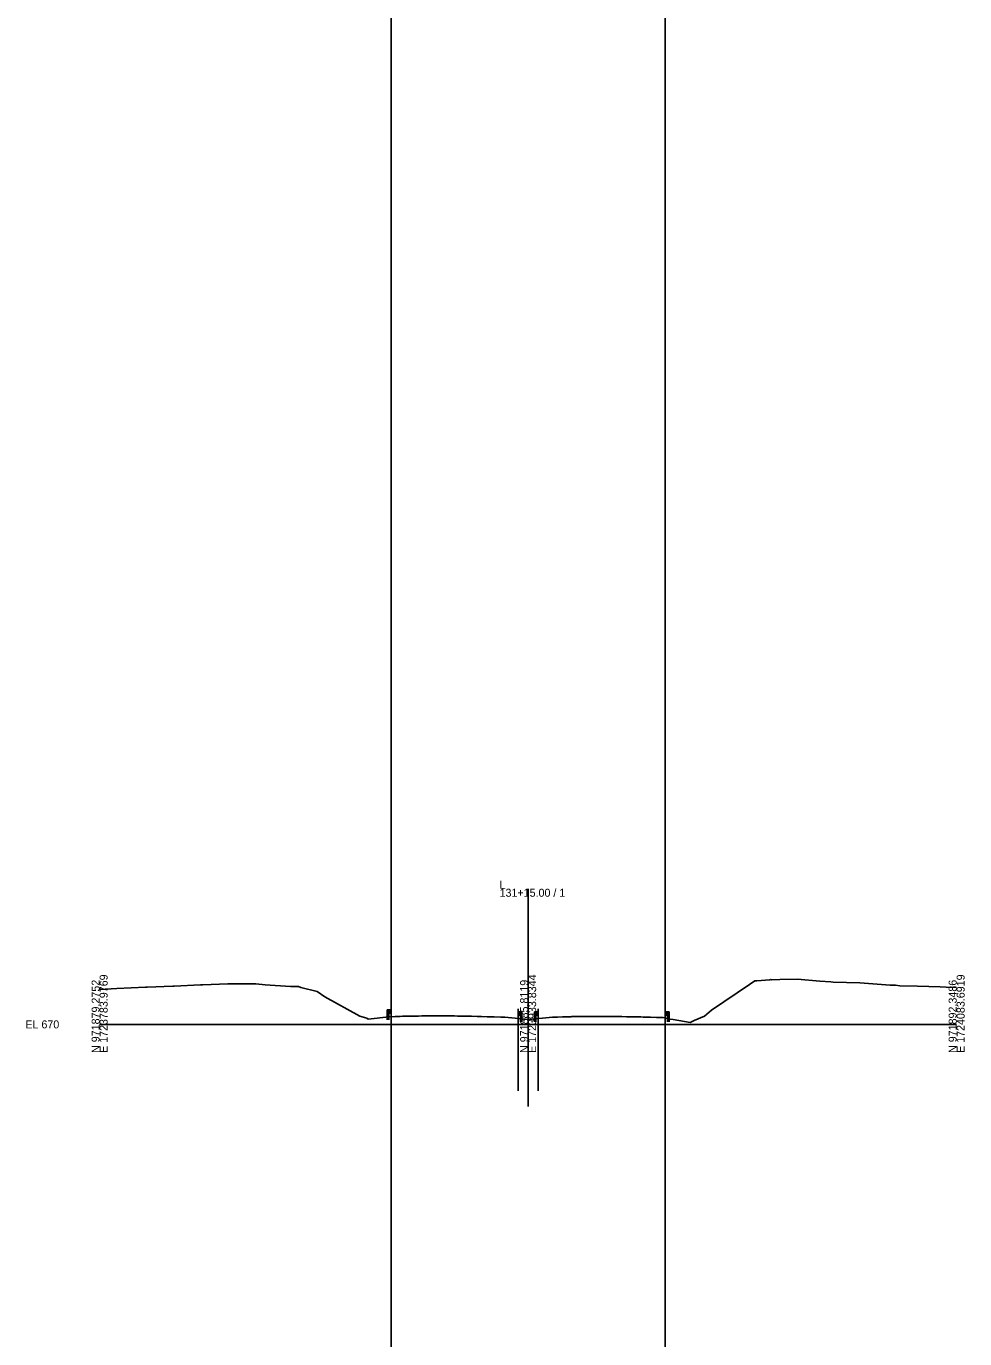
# Model space of a CAD drawing. Extents: x -26 to 303, y -29 to 15026.
# Drawn here: x -25.7 to 302.8, y 890 to 1349.3 of the extents above; entities that cross this region are included whole.
import ezdxf

# ---------------------------------------------------------------- set-up
doc = ezdxf.new("R2010")
doc.units = 0
for name, color, linetype in [('Exist Cross Section Cell', 7, 'Continuous'), ('Exist XS Center Line Elevation Label', 7, 'Continuous'), ('Exist XS Ground Line', 7, 'Continuous'), ('Scratch_Level_0', 7, 'Continuous'), ('Typical Guardrail CELL', 7, 'Continuous')]:
    doc.layers.add(name, color=color, linetype=linetype)

msp = doc.modelspace()

# ---------------------------------------------------------------- linework, layer by layer
at = {"layer": 'Exist Cross Section Cell'}
for p, q in [((150, 1000), (150, 1047.47)), ((0, 1000), (150, 1000)), ((150, 1000), (300, 1000))]:
    msp.add_line(p, q, dxfattribs=at)
at = {"layer": 'Exist XS Ground Line'}
msp.add_lwpolyline([(0, 1012.24), (6.04, 1012.58), (16.07, 1013.05), (16.68, 1013.07), (25.67, 1013.4), (26.06, 1013.41), (35.26, 1013.85), (36.07, 1013.89), (44.85, 1014.16), (46.52, 1014.19), (53.59, 1014.2), (54.66, 1014.22), (57.96, 1013.81), (66.81, 1013.3), (69.56, 1013.22), (70.38, 1012.9), (76.1, 1011.47), (78.82, 1009.59), (91.07, 1002.88), (93.5, 1002.17), (94.04, 1001.85), (101.24, 1002.61), (102.28, 1002.74), (102.9, 1002.7), (103.49, 1002.72), (105.22, 1002.81), (106, 1002.83), (107.72, 1002.88), (109.33, 1002.9), (110.23, 1002.91), (111.13, 1002.93), (111.66, 1002.93), (112.74, 1002.94), (113.82, 1002.95), (115.24, 1002.95), (116.44, 1002.96), (117.73, 1002.97), (119.05, 1002.98), (120.23, 1002.98), (121.31, 1002.98), (123.1, 1002.98), (124.18, 1002.96), (125.22, 1002.93), (126.88, 1002.9), (127.72, 1002.88), (129.51, 1002.84), (130.23, 1002.83), (132.16, 1002.78), (132.74, 1002.77), (133.28, 1002.75), (133.73, 1002.74), (135.69, 1002.68), (137.28, 1002.65), (137.77, 1002.63), (138.12, 1002.62), (140.49, 1002.57), (141.42, 1002.55), (141.84, 1002.51), (150.2, 1001.66), (158.53, 1002.54), (160.29, 1002.57), (162.08, 1002.62), (162.77, 1002.64), (163.57, 1002.67), (164.56, 1002.7), (164.89, 1002.7), (165.26, 1002.71), (166.89, 1002.72), (167.81, 1002.73), (168.79, 1002.74), (170.27, 1002.76), (171.67, 1002.77), (172.79, 1002.78), (174.01, 1002.79), (175.29, 1002.8), (176.76, 1002.8), (177.32, 1002.79), (178.29, 1002.78), (179.23, 1002.77), (180.28, 1002.75), (181.24, 1002.74), (182.78, 1002.71), (184.45, 1002.68), (185.27, 1002.67), (186.03, 1002.66), (187.79, 1002.63), (189.49, 1002.6), (190.28, 1002.57), (190.81, 1002.56), (192.81, 1002.51), (194.94, 1002.46), (195.45, 1002.45), (197.32, 1002.37), (198.25, 1002.16), (199.67, 1001.88), (200.74, 1001.72), (206.73, 1000.71), (208.16, 1001.37), (211.77, 1002.85), (214.23, 1004.96), (227.53, 1013.95), (229.3, 1015.26), (230.11, 1015.29), (234.56, 1015.59), (234.92, 1015.71), (235.26, 1015.65), (238.12, 1015.7), (244.33, 1015.82), (252.14, 1015.16), (256, 1014.88), (256.72, 1014.79), (266.15, 1014.56), (276.77, 1013.76), (278.63, 1013.68), (280.13, 1013.55), (286.29, 1013.35), (294.21, 1013.11), (296.3, 1012.99), (300, 1012.9)], dxfattribs=at)
at = {"layer": 'Scratch_Level_0'}
for p, q in [((102, 15009.56), (102, -28.7)), ((198, 15009.56), (198, -28.7)), ((146.46, 1005.5), (146.46, 976.8)), ((153.54, 1005.5), (153.54, 976.8)), ((150, 1000), (150, 971.3))]:
    msp.add_line(p, q, dxfattribs=at)
at = {"layer": 'Typical Guardrail CELL'}
for p, q in [((101.18, 1005.04), (100.68, 1005.04)), ((100.68, 1005.04), (100.68, 1002.55)), ((101.18, 1002.55), (100.68, 1002.55)), ((100.68, 1002.55), (100.68, 1001.54)), ((101.18, 1005.04), (101.18, 1002.55)), ((101.18, 1005.04), (101.68, 1005.04)), ((101.18, 1003.88), (101.68, 1003.88)), ((101.18, 1002.55), (101.18, 1001.54)), ((101.68, 1005.04), (101.68, 1003.88)), ((101.68, 1005.04), (101.97, 1004.83)), ((101.68, 1004.5), (101.97, 1004.71)), ((101.68, 1004.46), (101.68, 1004.5)), ((101.68, 1004.46), (101.68, 1004.41)), ((101.68, 1004.41), (101.97, 1004.21)), ((101.68, 1003.88), (101.97, 1004.08)), ((146.78, 1004.39), (146.49, 1004.19)), ((146.78, 1003.86), (146.49, 1004.06)), ((146.78, 1003.76), (146.49, 1003.56)), ((146.78, 1003.23), (146.49, 1003.43)), ((147.28, 1004.39), (146.78, 1004.39)), ((146.78, 1004.39), (146.78, 1003.23)), ((146.78, 1003.81), (146.78, 1003.86)), ((146.78, 1003.81), (146.78, 1003.76)), ((147.28, 1003.23), (146.78, 1003.23)), ((147.28, 1004.39), (147.28, 1001.9)), ((147.28, 1004.39), (147.78, 1004.39)), ((147.28, 1001.9), (147.78, 1001.9)), ((147.28, 1001.9), (147.28, 1000.9)), ((147.78, 1004.39), (147.78, 1001.9)), ((147.78, 1001.9), (147.78, 1000.9)), ((152.72, 1004.36), (152.22, 1004.36)), ((152.22, 1004.36), (152.22, 1001.87)), ((152.72, 1001.87), (152.22, 1001.87)), ((152.22, 1001.87), (152.22, 1000.86)), ((152.72, 1004.36), (152.72, 1001.87)), ((152.72, 1004.36), (153.22, 1004.36)), ((152.72, 1003.2), (153.22, 1003.2)), ((152.72, 1001.87), (152.72, 1000.86)), ((153.22, 1004.36), (153.22, 1003.2)), ((153.22, 1004.36), (153.51, 1004.15)), ((153.22, 1003.82), (153.51, 1004.03)), ((153.22, 1003.78), (153.22, 1003.82)), ((153.22, 1003.78), (153.22, 1003.73)), ((153.22, 1003.73), (153.51, 1003.53)), ((153.22, 1003.2), (153.51, 1003.4)), ((198.32, 1004.43), (198.03, 1004.23)), ((198.32, 1003.9), (198.03, 1004.1)), ((198.32, 1003.81), (198.03, 1003.6)), ((198.32, 1003.27), (198.03, 1003.48)), ((198.82, 1004.43), (198.32, 1004.43)), ((198.32, 1004.43), (198.32, 1003.27)), ((198.32, 1003.85), (198.32, 1003.9)), ((198.32, 1003.85), (198.32, 1003.81)), ((198.82, 1003.27), (198.32, 1003.27)), ((198.82, 1004.43), (198.82, 1001.95)), ((198.82, 1004.43), (199.32, 1004.43)), ((198.82, 1001.95), (199.32, 1001.95)), ((198.82, 1001.95), (198.82, 1000.94)), ((199.32, 1004.43), (199.32, 1001.95)), ((199.32, 1001.95), (199.32, 1000.94))]:
    msp.add_line(p, q, dxfattribs=at)
for centre, start, end in [((101.92, 1004.77), 304.9888, 54.997), ((101.92, 1004.14), 304.9634, 54.9941), ((146.54, 1004.12), 125.003, 235.0112), ((146.54, 1003.5), 125.0059, 235.0366), ((153.46, 1004.09), 304.9888, 54.997), ((153.46, 1003.46), 304.9634, 54.9941), ((198.08, 1004.17), 125.003, 235.0112), ((198.08, 1003.54), 125.0059, 235.0366)]:
    msp.add_arc(centre, 0.0776, start, end, dxfattribs=at)

# ---------------------------------------------------------------- texts
at = {"layer": 'Exist Cross Section Cell'}
for s, p in [('131+15.00 / 1', (140, 1044.67)), ('L', (140, 1047.47)), ('EL 670', (-26, 998.6))]:
    msp.add_text(s, height=2.8, dxfattribs=at).set_placement(p)
for s, p in [('N 971879.2752', (0, 990)), ('E 1723783.9769', (2.8, 990)), ('N 971885.8119', (150, 990)), ('E 1723933.8344', (152.8, 990)), ('N 971892.3486', (300, 990)), ('E 1724083.6919', (302.8, 990))]:
    msp.add_text(s, height=2.8, rotation=90, dxfattribs=at).set_placement(p)
at = {"layer": 'Exist XS Center Line Elevation Label'}
msp.add_text('671.68', height=0.18, dxfattribs=at).set_placement((149.64, 1001.19))

doc.saveas('drawing.dxf')
